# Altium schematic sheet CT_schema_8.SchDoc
size 281 x 153 mm
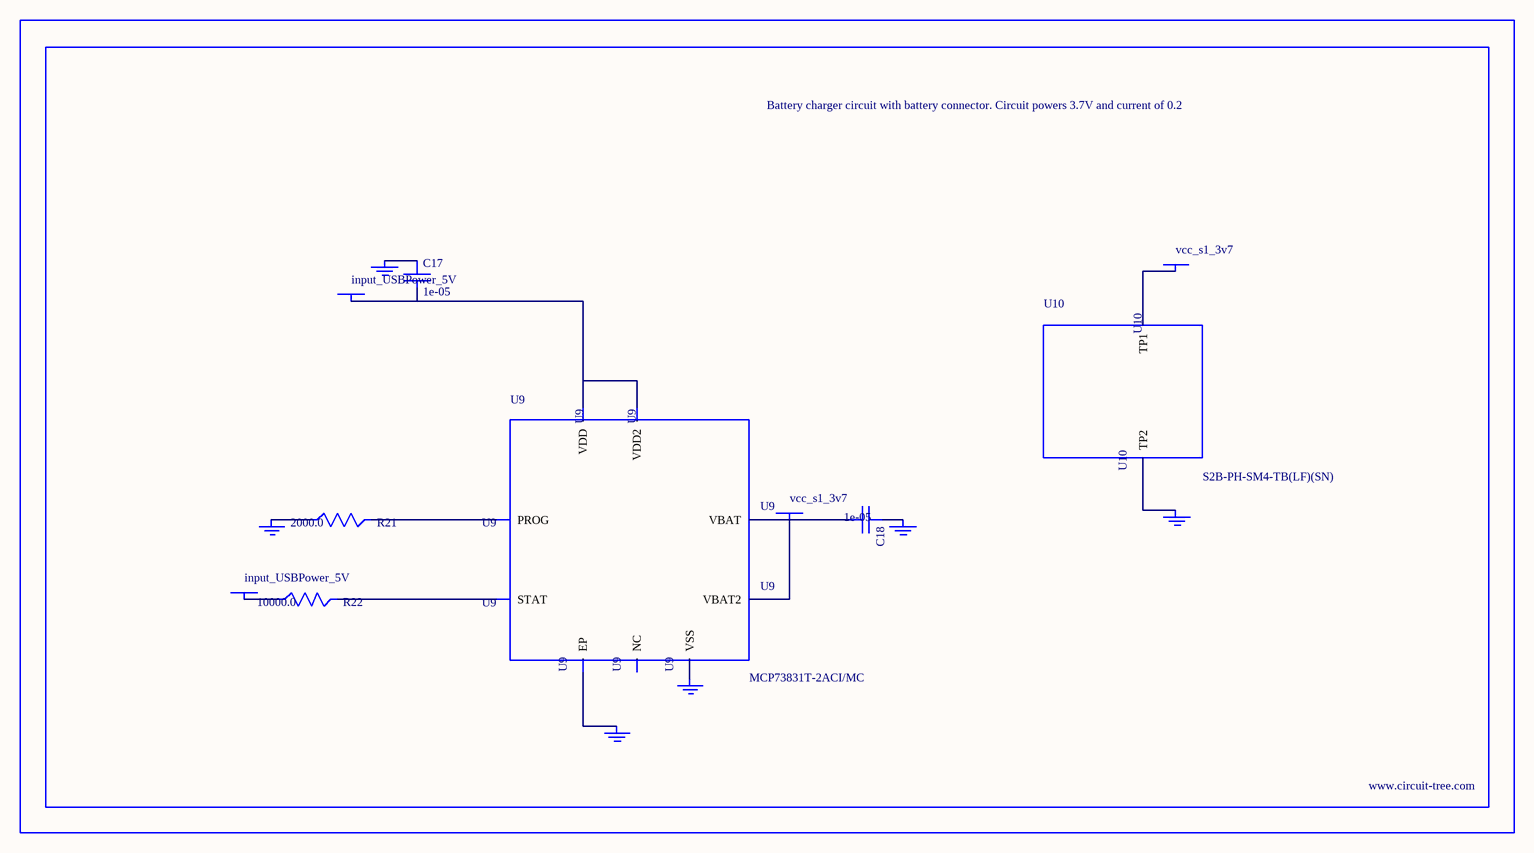
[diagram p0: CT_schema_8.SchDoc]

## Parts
BORDER7  (no value)
C17  1e-05  [C1206]
C18  1e-05  [C1206]
GND_INSTANCE_7_0  (no value)
GND_INSTANCE_7_1  (no value)
GND_INSTANCE_7_2  (no value)
GND_INSTANCE_7_3  (no value)
GND_INSTANCE_7_4  (no value)
GND_INSTANCE_7_5  (no value)
POWER_INSTANCE_7_0  input_USBPower_5V
POWER_INSTANCE_7_1  input_USBPower_5V
POWER_INSTANCE_7_2  vcc_s1_3v7
POWER_INSTANCE_7_3  vcc_s1_3v7
R21  2000.0  [R0603]
R22  10000.0  [R0603]
U9  MCP73831T-2ACI/MC  [DFN8_2X3MC]
U10  S2B-PH-SM4-TB(LF)(SN)  [JST-2-SMD]

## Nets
NetC17_1: C17.1 GND_INSTANCE_7_0.0(GND)
NetC17_2: C17.2 POWER_INSTANCE_7_0.0(PWR) U9.1(VDD) U9.2(VDD2)
NetC18_1: C18.1 GND_INSTANCE_7_1.0(GND)
NetC18_2: C18.2 POWER_INSTANCE_7_2.0(PWR) U9.3(VBAT) U9.4(VBAT2)
NetGND_INSTANCE_7_2_0: GND_INSTANCE_7_2.0(GND) R21.1
NetGND_INSTANCE_7_3_0: GND_INSTANCE_7_3.0(GND) U9.9(EP)
NetGND_INSTANCE_7_4_0: GND_INSTANCE_7_4.0(GND) U9.6(VSS)
NetGND_INSTANCE_7_5_0: GND_INSTANCE_7_5.0(GND) U10.2(TP2)
NetPOWER_INSTANCE_7_1_0: POWER_INSTANCE_7_1.0(PWR) R22.1
NetPOWER_INSTANCE_7_3_0: POWER_INSTANCE_7_3.0(PWR) U10.1(TP1)
NetR21_2: R21.2 U9.8(PROG)
NetR22_2: R22.2 U9.5(STAT)

Not connected (* = marked no-connect by the designer): U9 7(NC)

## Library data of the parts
BORDER7 = BORDER_PAGE7
C17 C18 = C1206C106K3RACTU
GND_INSTANCE_7_0-GND_INSTANCE_7_5 = GND
POWER_INSTANCE_7_0-POWER_INSTANCE_7_3 = PWR
R21 = RC0603JR-072KL
R22 = RC0603JR-0710KL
